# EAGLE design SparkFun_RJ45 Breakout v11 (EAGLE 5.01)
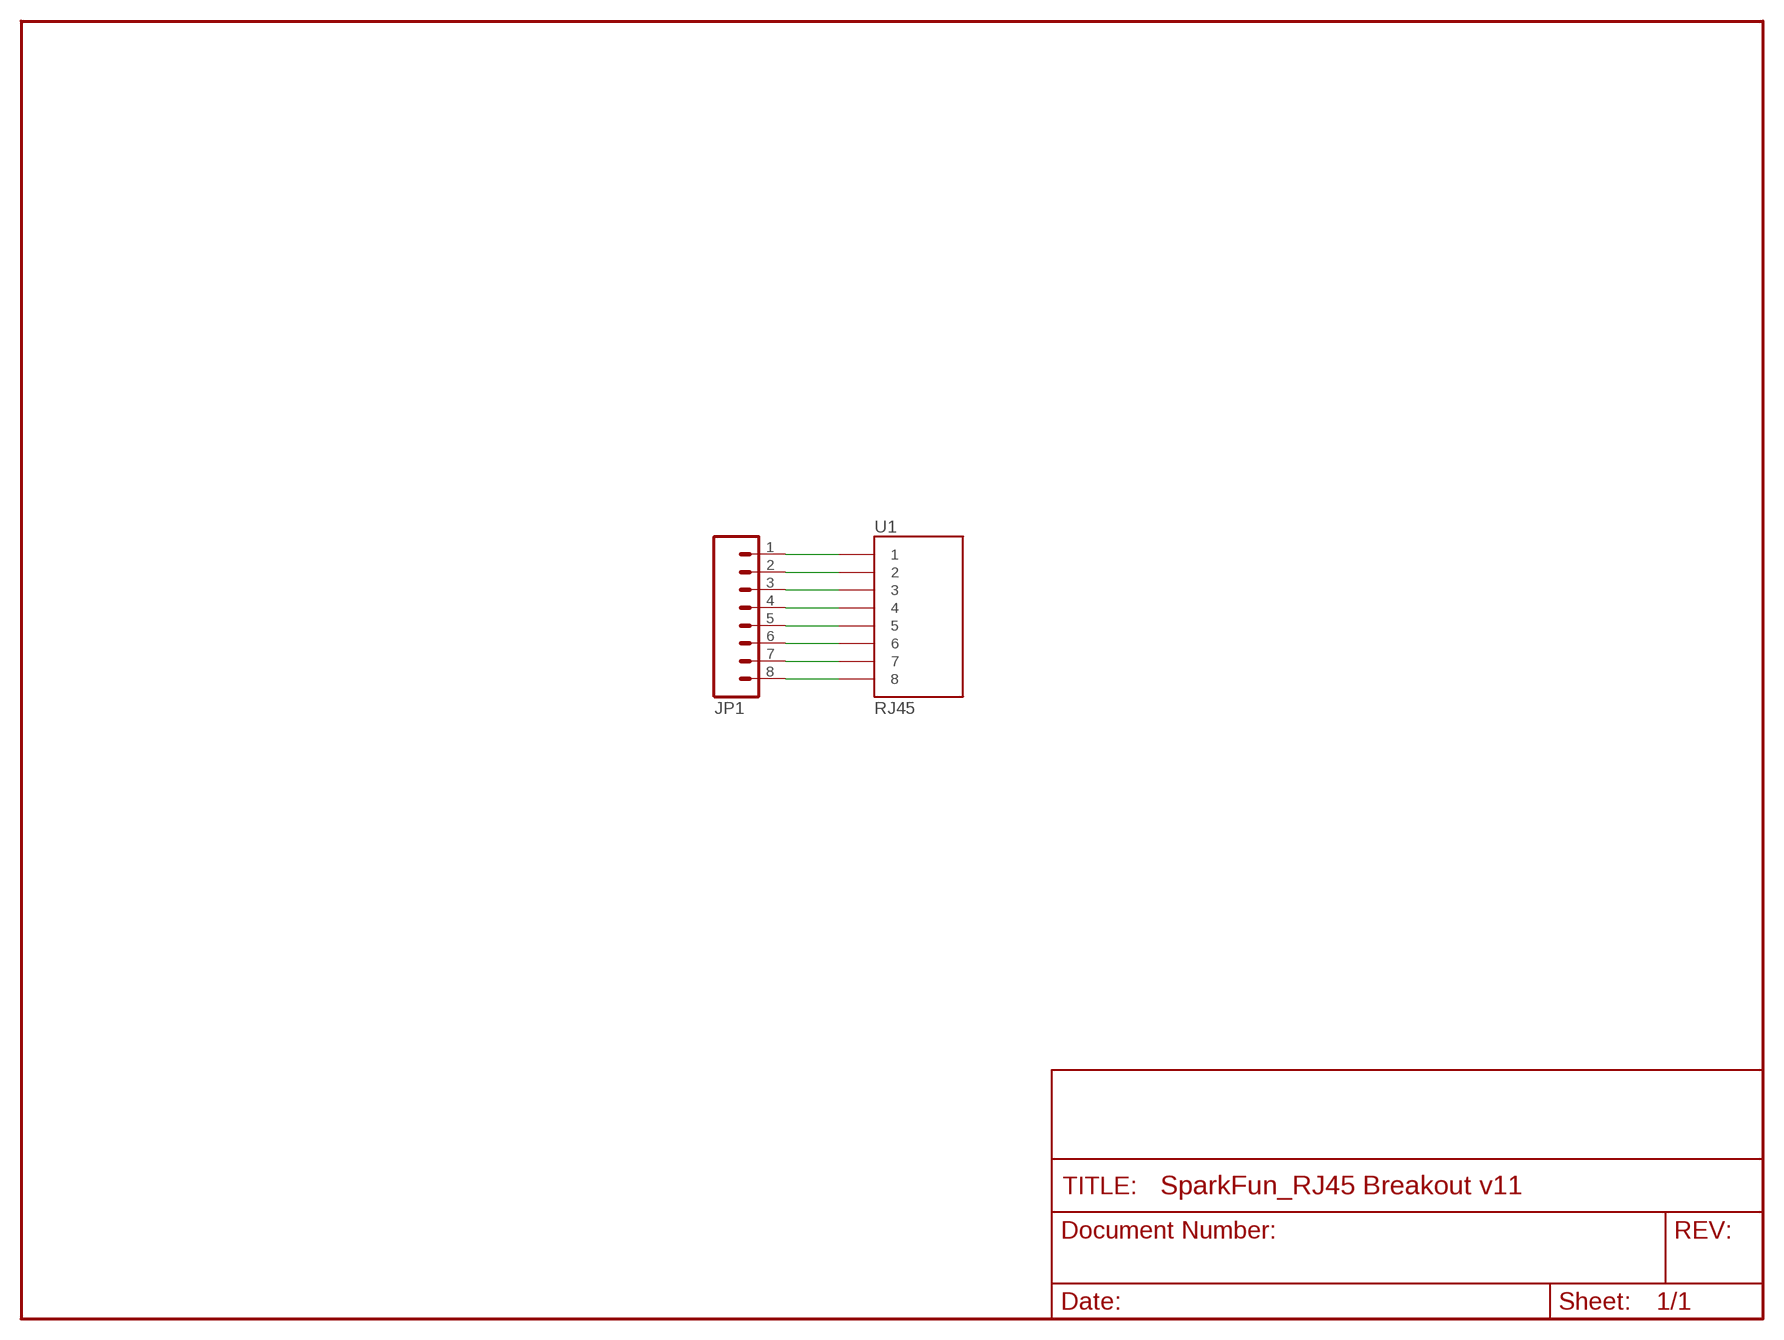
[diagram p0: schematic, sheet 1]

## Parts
JP1  M08  [1X08]
U1  RJ45  RJ45-8PTH  [RJ45-8]

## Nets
N$1: JP1.1 U1.1
N$2: JP1.2 U1.2
N$3: JP1.3 U1.3
N$4: JP1.4 U1.4
N$5: JP1.5 U1.5
N$6: JP1.6 U1.6
N$7: JP1.7 U1.7
N$8: JP1.8 U1.8

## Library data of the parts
JP1 = SparkFun:M08: Header 8 Standard 8-pin 0.1" header. Use with straight break away headers (SKU : PRT-00116), right angle break away headers (PRT-00553), swiss pins (PRT-00743), machine pins (PRT-00117), and female headers (PRT-00115).
U1 = SparkFun:RJ45-8: RJ45 Jack Simple RJ45, 8-pin connection - connector for common Cat5, Cat5e, and Cat6 Ethernet cables. Footprint not yet proven in production. Connector sku is PRT-00643; Breakout PCB sku is BOB-00716.

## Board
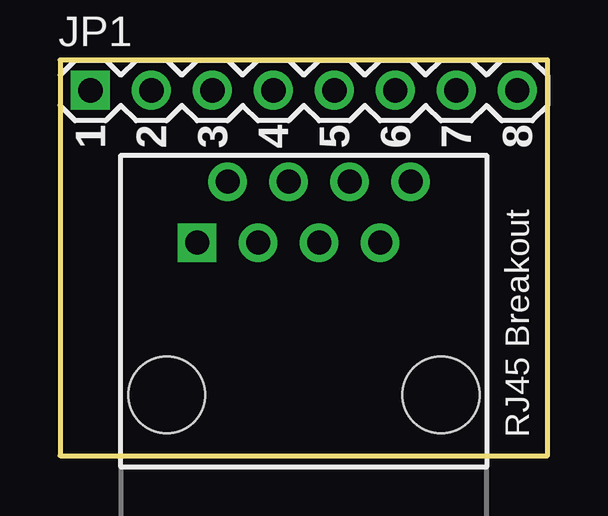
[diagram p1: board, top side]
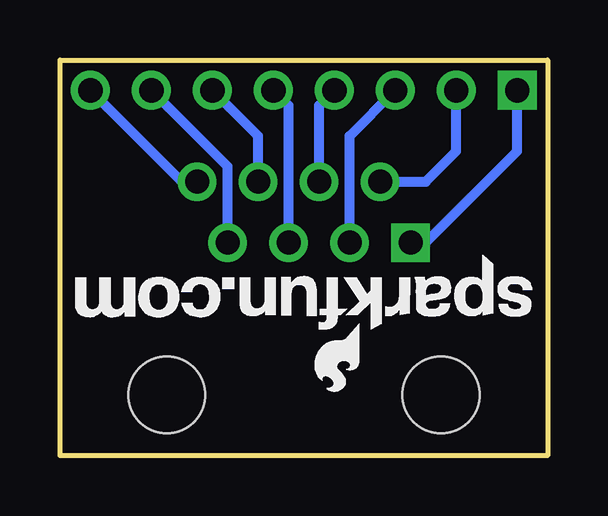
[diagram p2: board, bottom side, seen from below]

Size 20.32 x 16.51 mm. Coordinates in mm from the lower left corner, seen from the top.
Outline: 0,0 20.32,0 20.32,16.51 0,16.51 0,0
Copper layers (1*16): Top 0.035mm / dielectric 1.5mm / Bottom 0.035mm
Design rules "SparkFun": minimum track width 8mil, minimum drill 20mil, track to track 8mil, track to pad 8mil, pad to pad 8mil, via to via 8mil, smd to smd 8mil, copper to edge 10mil, drill to drill 8mil, minimum pad ring 12mil, minimum via ring 10mil, stop-mask expansion 4mil, vias tented up to drill 20mil, thermal gap 10mil

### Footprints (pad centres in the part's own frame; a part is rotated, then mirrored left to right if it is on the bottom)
1X08 = drill 1.016 square: 1 0,0 | drill 1.016 round: 2 2.54,0; 3 5.08,0; 4 7.62,0; 5 10.16,0; 6 12.7,0; 7 15.24,0; 8 17.78,0
RJ45-8 = drill 1 square: 1 -4.445,6.35 | drill 1 round: 2 -3.175,8.89; 3 -1.905,6.35; 4 -0.635,8.89; 5 0.635,6.35; 6 1.905,8.89; 7 3.175,6.35; 8 4.445,8.89 | hole 3.2: -5.715,0; 5.715,0

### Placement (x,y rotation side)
JP1  1.27,15.24 0 top
U1  10.16,2.54 0 top
U$2  [SFE-NEW-WEBLOGO]  0.64,8.38 180 bottom

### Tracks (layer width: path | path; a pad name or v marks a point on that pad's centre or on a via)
N$1
  Bottom 0.406: U1.1 5.08,8.89 1.27,12.7 JP1.1
N$2
  Bottom 0.406: U1.2 5.08,11.43 3.81,12.7 JP1.2
N$3
  Bottom 0.406: U1.3 8.26,13.34 JP1.3
N$4
  Bottom 0.406: U1.4 9.53,14.61 JP1.4
N$5
  Bottom 0.406: U1.5 10.79,14.61 JP1.5
N$6
  Bottom 0.406: U1.6 12.06,13.34 JP1.6
N$7
  Bottom 0.406: U1.7 13.34,12.06 JP1.7
N$8
  Bottom 0.406: U1.8 15.24,11.43 JP1.8

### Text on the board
tPlace: 1 | 2 | 3 | 4 | 5 | 6 | 7 | 8 | RJ45 Breakout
